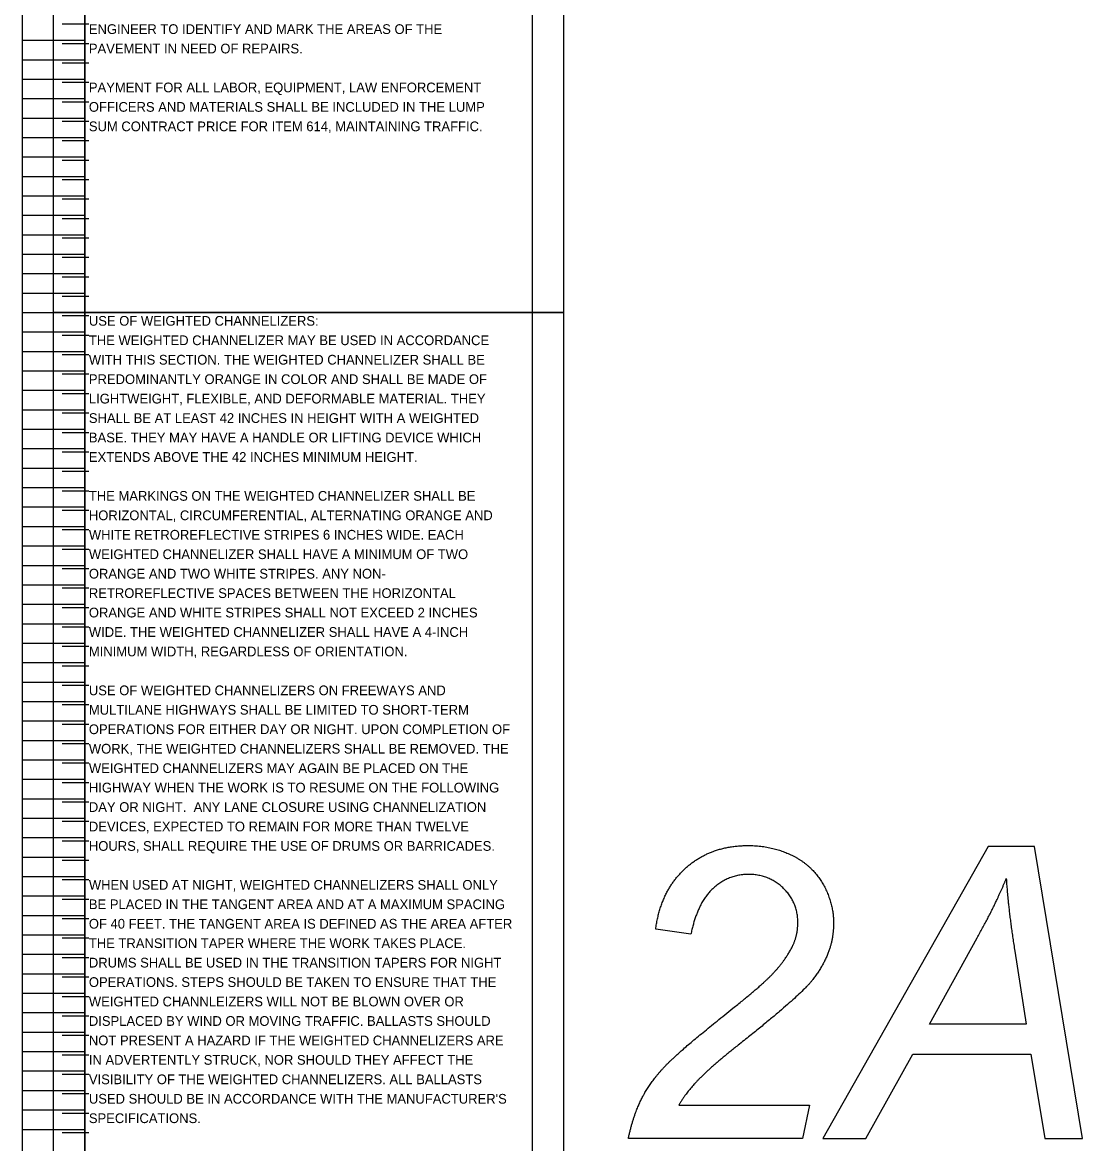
# Model space of a CAD drawing. Extents: x 12522 to 12538, y 1124 to 1850.
# Drawn here: x 12521.92 to 12537.18, y 1757.19 to 1773.33 of the extents above; entities that cross this region are included whole.
import ezdxf

# ---------------------------------------------------------------- set-up
doc = ezdxf.new("R2010")
doc.units = 0
doc.layers.add('SC_Scratch1', color=7, linetype='Continuous')
doc.layers.add('SH_Text', color=7, linetype='Continuous')

msp = doc.modelspace()

# ---------------------------------------------------------------- linework, layer by layer
at = {"layer": 'SC_Scratch1'}
for p, q in [((12521.919, 1769.151), (12521.919, 1789.311)), ((12522.819, 1769.151), (12522.819, 1789.311)), ((12522.819, 1789.311), (12522.819, 1769.151)), ((12522.876, 1773.301), (12522.492, 1773.301)), ((12521.919, 1773.071), (12522.819, 1773.071)), ((12522.876, 1773.021), (12522.492, 1773.021)), ((12521.919, 1772.791), (12522.819, 1772.791)), ((12522.876, 1772.741), (12522.492, 1772.741)), ((12521.919, 1772.511), (12522.819, 1772.511)), ((12522.876, 1772.461), (12522.492, 1772.461)), ((12521.919, 1772.231), (12522.819, 1772.231)), ((12522.876, 1772.181), (12522.492, 1772.181)), ((12521.919, 1771.951), (12522.819, 1771.951)), ((12522.876, 1771.901), (12522.492, 1771.901)), ((12521.919, 1771.671), (12522.819, 1771.671)), ((12522.876, 1771.621), (12522.492, 1771.621)), ((12521.919, 1771.391), (12522.819, 1771.391)), ((12522.876, 1771.341), (12522.492, 1771.341)), ((12521.919, 1771.111), (12522.819, 1771.111)), ((12522.876, 1771.061), (12522.492, 1771.061)), ((12521.919, 1770.831), (12522.819, 1770.831)), ((12522.876, 1770.781), (12522.492, 1770.781)), ((12521.919, 1770.551), (12522.819, 1770.551)), ((12522.876, 1770.501), (12522.492, 1770.501)), ((12521.919, 1770.271), (12522.819, 1770.271)), ((12522.876, 1770.221), (12522.492, 1770.221)), ((12521.919, 1769.991), (12522.819, 1769.991)), ((12522.876, 1769.941), (12522.492, 1769.941)), ((12521.919, 1769.711), (12522.819, 1769.711)), ((12522.876, 1769.661), (12522.492, 1769.661)), ((12521.919, 1769.431), (12522.819, 1769.431)), ((12522.876, 1769.381), (12522.492, 1769.381)), ((12522.819, 1769.381), (12522.819, 1728.831)), ((12521.919, 1769.151), (12522.819, 1769.151)), ((12521.919, 1748.991), (12521.919, 1769.151)), ((12521.919, 1769.151), (12522.819, 1769.151)), ((12522.876, 1769.101), (12522.492, 1769.101)), ((12522.819, 1748.991), (12522.819, 1769.151)), ((12521.919, 1768.871), (12522.819, 1768.871)), ((12522.876, 1768.821), (12522.492, 1768.821)), ((12521.919, 1768.591), (12522.819, 1768.591)), ((12522.876, 1768.541), (12522.492, 1768.541)), ((12521.919, 1768.311), (12522.819, 1768.311)), ((12522.876, 1768.261), (12522.492, 1768.261)), ((12521.919, 1768.031), (12522.819, 1768.031)), ((12522.876, 1767.981), (12522.492, 1767.981)), ((12521.919, 1767.751), (12522.819, 1767.751)), ((12522.876, 1767.701), (12522.492, 1767.701)), ((12521.919, 1767.471), (12522.819, 1767.471)), ((12522.876, 1767.421), (12522.492, 1767.421)), ((12521.919, 1767.191), (12522.819, 1767.191)), ((12522.876, 1767.141), (12522.492, 1767.141)), ((12521.919, 1766.911), (12522.819, 1766.911)), ((12522.876, 1766.861), (12522.492, 1766.861)), ((12521.919, 1766.631), (12522.819, 1766.631)), ((12522.876, 1766.581), (12522.492, 1766.581)), ((12521.919, 1766.351), (12522.819, 1766.351)), ((12522.876, 1766.301), (12522.492, 1766.301)), ((12521.919, 1766.071), (12522.819, 1766.071)), ((12522.876, 1766.021), (12522.492, 1766.021)), ((12521.919, 1765.791), (12522.819, 1765.791)), ((12522.876, 1765.741), (12522.492, 1765.741)), ((12521.919, 1765.511), (12522.819, 1765.511)), ((12522.876, 1765.461), (12522.492, 1765.461)), ((12521.919, 1765.231), (12522.819, 1765.231)), ((12522.876, 1765.181), (12522.492, 1765.181)), ((12521.919, 1764.951), (12522.819, 1764.951)), ((12522.876, 1764.901), (12522.492, 1764.901)), ((12521.919, 1764.671), (12522.819, 1764.671)), ((12522.876, 1764.621), (12522.492, 1764.621)), ((12521.919, 1764.391), (12522.819, 1764.391)), ((12522.876, 1764.341), (12522.492, 1764.341)), ((12521.919, 1764.111), (12522.819, 1764.111)), ((12522.876, 1764.061), (12522.492, 1764.061)), ((12521.919, 1763.831), (12522.819, 1763.831)), ((12522.876, 1763.781), (12522.492, 1763.781)), ((12521.919, 1763.551), (12522.819, 1763.551)), ((12522.876, 1763.501), (12522.492, 1763.501)), ((12521.919, 1763.271), (12522.819, 1763.271)), ((12522.876, 1763.221), (12522.492, 1763.221)), ((12521.919, 1762.991), (12522.819, 1762.991)), ((12522.876, 1762.941), (12522.492, 1762.941)), ((12521.919, 1762.711), (12522.819, 1762.711)), ((12522.876, 1762.661), (12522.492, 1762.661)), ((12521.919, 1762.431), (12522.819, 1762.431)), ((12522.876, 1762.381), (12522.492, 1762.381)), ((12521.919, 1762.151), (12522.819, 1762.151)), ((12522.876, 1762.101), (12522.492, 1762.101)), ((12521.919, 1761.871), (12522.819, 1761.871)), ((12522.876, 1761.821), (12522.492, 1761.821)), ((12521.919, 1761.591), (12522.819, 1761.591)), ((12522.876, 1761.541), (12522.492, 1761.541)), ((12521.919, 1761.311), (12522.819, 1761.311)), ((12522.876, 1761.261), (12522.492, 1761.261)), ((12521.919, 1761.031), (12522.819, 1761.031)), ((12522.876, 1760.981), (12522.492, 1760.981)), ((12521.919, 1760.751), (12522.819, 1760.751)), ((12522.876, 1760.701), (12522.492, 1760.701)), ((12521.919, 1760.471), (12522.819, 1760.471)), ((12522.876, 1760.421), (12522.492, 1760.421)), ((12531.543, 1760.199), (12531.037, 1760.274)), ((12521.919, 1760.191), (12522.819, 1760.191)), ((12522.876, 1760.141), (12522.492, 1760.141)), ((12521.919, 1759.911), (12522.819, 1759.911)), ((12522.876, 1759.861), (12522.492, 1759.861)), ((12521.919, 1759.631), (12522.819, 1759.631)), ((12522.876, 1759.581), (12522.492, 1759.581)), ((12521.919, 1759.351), (12522.819, 1759.351)), ((12522.876, 1759.301), (12522.492, 1759.301)), ((12521.919, 1759.071), (12522.819, 1759.071)), ((12522.876, 1759.021), (12522.492, 1759.021)), ((12521.919, 1758.791), (12522.819, 1758.791)), ((12522.876, 1758.741), (12522.492, 1758.741)), ((12521.919, 1758.511), (12522.819, 1758.511)), ((12522.876, 1758.461), (12522.492, 1758.461)), ((12521.919, 1758.231), (12522.819, 1758.231)), ((12522.876, 1758.181), (12522.492, 1758.181)), ((12521.919, 1757.951), (12522.819, 1757.951)), ((12522.876, 1757.901), (12522.492, 1757.901)), ((12521.919, 1757.671), (12522.819, 1757.671)), ((12522.876, 1757.621), (12522.492, 1757.621)), ((12521.919, 1757.391), (12522.819, 1757.391)), ((12522.876, 1757.341), (12522.492, 1757.341))]:
    msp.add_line(p, q, dxfattribs=at)
for points in [[(12522.369, 1789.311), (12529.709, 1789.311), (12529.709, 1769.151), (12522.369, 1769.151)], [(12522.819, 1789.311), (12529.259, 1789.311), (12529.259, 1769.151), (12522.819, 1769.151)], [(12522.369, 1769.151), (12529.709, 1769.151), (12529.709, 1748.991), (12522.369, 1748.991)], [(12522.819, 1769.151), (12529.259, 1769.151), (12529.259, 1748.991), (12522.819, 1748.991)], [(12533.445, 1757.261), (12534.061, 1757.261), (12534.737, 1758.471), (12536.436, 1758.471), (12536.638, 1757.261), (12537.182, 1757.261), (12536.489, 1761.461), (12535.824, 1761.461)]]:
    msp.add_lwpolyline(points, close=True, dxfattribs=at)
for points in [[(12536.206, 1759.958), (12536.369, 1758.903), (12534.979, 1758.903), (12535.665, 1760.147)], [(12531.369, 1757.738), (12533.249, 1757.738), (12533.149, 1757.261), (12530.643, 1757.261)]]:
    msp.add_lwpolyline(points, dxfattribs=at)
for points in [[(12531.471, 1761.155), (12531.831, 1761.477), (12532.366, 1761.477)], [(12532.366, 1761.477), (12532.724, 1761.477), (12533.015, 1761.328)], [(12533.015, 1761.328), (12533.306, 1761.179), (12533.452, 1760.91)], [(12531.037, 1760.274), (12531.111, 1760.832), (12531.471, 1761.155)], [(12532.374, 1761.061), (12532.079, 1761.061), (12531.858, 1760.856)], [(12532.878, 1760.859), (12532.673, 1761.061), (12532.374, 1761.061)], [(12531.858, 1760.856), (12531.637, 1760.651), (12531.543, 1760.199)], [(12533.083, 1760.368), (12533.083, 1760.657), (12532.878, 1760.859)], [(12533.452, 1760.91), (12533.598, 1760.641), (12533.598, 1760.354)], [(12535.665, 1760.147), (12535.94, 1760.642), (12536.084, 1761.003)], [(12536.084, 1761.003), (12536.108, 1760.585), (12536.206, 1759.958)], [(12533.017, 1760.05), (12533.083, 1760.196), (12533.083, 1760.368)], [(12533.598, 1760.354), (12533.598, 1759.936), (12533.3, 1759.549)], [(12532.704, 1759.612), (12532.919, 1759.836), (12533.017, 1760.05)], [(12532.148, 1759.134), (12532.555, 1759.458), (12532.704, 1759.612)], [(12533.3, 1759.549), (12533.117, 1759.309), (12532.223, 1758.602)], [(12531.242, 1758.371), (12531.477, 1758.599), (12532.148, 1759.134)], [(12532.223, 1758.602), (12531.839, 1758.299), (12531.651, 1758.104)], [(12530.865, 1757.89), (12531.007, 1758.144), (12531.242, 1758.371)], [(12531.651, 1758.104), (12531.463, 1757.91), (12531.369, 1757.738)], [(12530.643, 1757.261), (12530.724, 1757.636), (12530.865, 1757.89)]]:
    msp.add_open_spline(points, degree=2, dxfattribs=at)

# ---------------------------------------------------------------- texts
at = {"layer": 'SH_Text'}
for s, p in [('ENGINEER TO IDENTIFY AND MARK THE AREAS OF THE ', (12522.876, 1773.161)), ('PAVEMENT IN NEED OF REPAIRS.', (12522.876, 1772.881)), ('PAYMENT FOR ALL LABOR, EQUIPMENT, LAW ENFORCEMENT ', (12522.876, 1772.321)), ('OFFICERS AND MATERIALS SHALL BE INCLUDED IN THE LUMP ', (12522.876, 1772.041)), ('SUM CONTRACT PRICE FOR ITEM 614, MAINTAINING TRAFFIC.', (12522.876, 1771.761)), ('USE OF WEIGHTED CHANNELIZERS:', (12522.876, 1768.961)), ('THE WEIGHTED CHANNELIZER MAY BE USED IN ACCORDANCE ', (12522.876, 1768.681)), ('WITH THIS SECTION. THE WEIGHTED CHANNELIZER SHALL BE ', (12522.876, 1768.401)), ('PREDOMINANTLY ORANGE IN COLOR AND SHALL BE MADE OF ', (12522.876, 1768.121)), ('LIGHTWEIGHT, FLEXIBLE, AND DEFORMABLE MATERIAL. THEY ', (12522.876, 1767.841)), ('SHALL BE AT LEAST 42 INCHES IN HEIGHT WITH A WEIGHTED ', (12522.876, 1767.561)), ('BASE. THEY MAY HAVE A HANDLE OR LIFTING DEVICE WHICH ', (12522.876, 1767.281)), ('EXTENDS ABOVE THE 42 INCHES MINIMUM HEIGHT.', (12522.876, 1767.001)), ('THE MARKINGS ON THE WEIGHTED CHANNELIZER SHALL BE ', (12522.876, 1766.441)), ('HORIZONTAL, CIRCUMFERENTIAL, ALTERNATING ORANGE AND ', (12522.876, 1766.161)), ('WHITE RETROREFLECTIVE STRIPES 6 INCHES WIDE. EACH ', (12522.876, 1765.881)), ('WEIGHTED CHANNELIZER SHALL HAVE A MINIMUM OF TWO ', (12522.876, 1765.601)), ('ORANGE AND TWO WHITE STRIPES. ANY NON-', (12522.876, 1765.321)), ('RETROREFLECTIVE SPACES BETWEEN THE HORIZONTAL ', (12522.876, 1765.041)), ('ORANGE AND WHITE STRIPES SHALL NOT EXCEED 2 INCHES ', (12522.876, 1764.761)), ('WIDE. THE WEIGHTED CHANNELIZER SHALL HAVE A 4-INCH ', (12522.876, 1764.481)), ('MINIMUM WIDTH, REGARDLESS OF ORIENTATION.', (12522.876, 1764.201)), ('USE OF WEIGHTED CHANNELIZERS ON FREEWAYS AND ', (12522.876, 1763.641)), ('MULTILANE HIGHWAYS SHALL BE LIMITED TO SHORT-TERM ', (12522.876, 1763.361)), ('OPERATIONS FOR EITHER DAY OR NIGHT. UPON COMPLETION OF ', (12522.876, 1763.081)), ('WORK, THE WEIGHTED CHANNELIZERS SHALL BE REMOVED. THE ', (12522.876, 1762.801)), ('WEIGHTED CHANNELIZERS MAY AGAIN BE PLACED ON THE ', (12522.876, 1762.521)), ('HIGHWAY WHEN THE WORK IS TO RESUME ON THE FOLLOWING ', (12522.876, 1762.241)), ('DAY OR NIGHT.  ANY LANE CLOSURE USING CHANNELIZATION ', (12522.876, 1761.961)), ('DEVICES, EXPECTED TO REMAIN FOR MORE THAN TWELVE ', (12522.876, 1761.681)), ('HOURS, SHALL REQUIRE THE USE OF DRUMS OR BARRICADES.', (12522.876, 1761.401)), ('WHEN USED AT NIGHT, WEIGHTED CHANNELIZERS SHALL ONLY ', (12522.876, 1760.841)), ('BE PLACED IN THE TANGENT AREA AND AT A MAXIMUM SPACING ', (12522.876, 1760.561)), ('OF 40 FEET. THE TANGENT AREA IS DEFINED AS THE AREA AFTER ', (12522.876, 1760.281)), ('THE TRANSITION TAPER WHERE THE WORK TAKES PLACE. ', (12522.876, 1760.001)), ('DRUMS SHALL BE USED IN THE TRANSITION TAPERS FOR NIGHT ', (12522.876, 1759.721)), ('OPERATIONS. STEPS SHOULD BE TAKEN TO ENSURE THAT THE ', (12522.876, 1759.441)), ('WEIGHTED CHANNLEIZERS WILL NOT BE BLOWN OVER OR ', (12522.876, 1759.161)), ('DISPLACED BY WIND OR MOVING TRAFFIC. BALLASTS SHOULD ', (12522.876, 1758.881)), ('NOT PRESENT A HAZARD IF THE WEIGHTED CHANNELIZERS ARE ', (12522.876, 1758.601)), ('IN ADVERTENTLY STRUCK, NOR SHOULD THEY AFFECT THE ', (12522.876, 1758.321)), ('VISIBILITY OF THE WEIGHTED CHANNELIZERS. ALL BALLASTS ', (12522.876, 1758.041)), ("USED SHOULD BE IN ACCORDANCE WITH THE MANUFACTURER'S ", (12522.876, 1757.761)), ('SPECIFICATIONS.', (12522.876, 1757.481))]:
    msp.add_text(s, height=0.14, dxfattribs=at).set_placement(p)

doc.saveas('drawing.dxf')
